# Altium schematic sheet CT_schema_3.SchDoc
size 573 x 363 mm
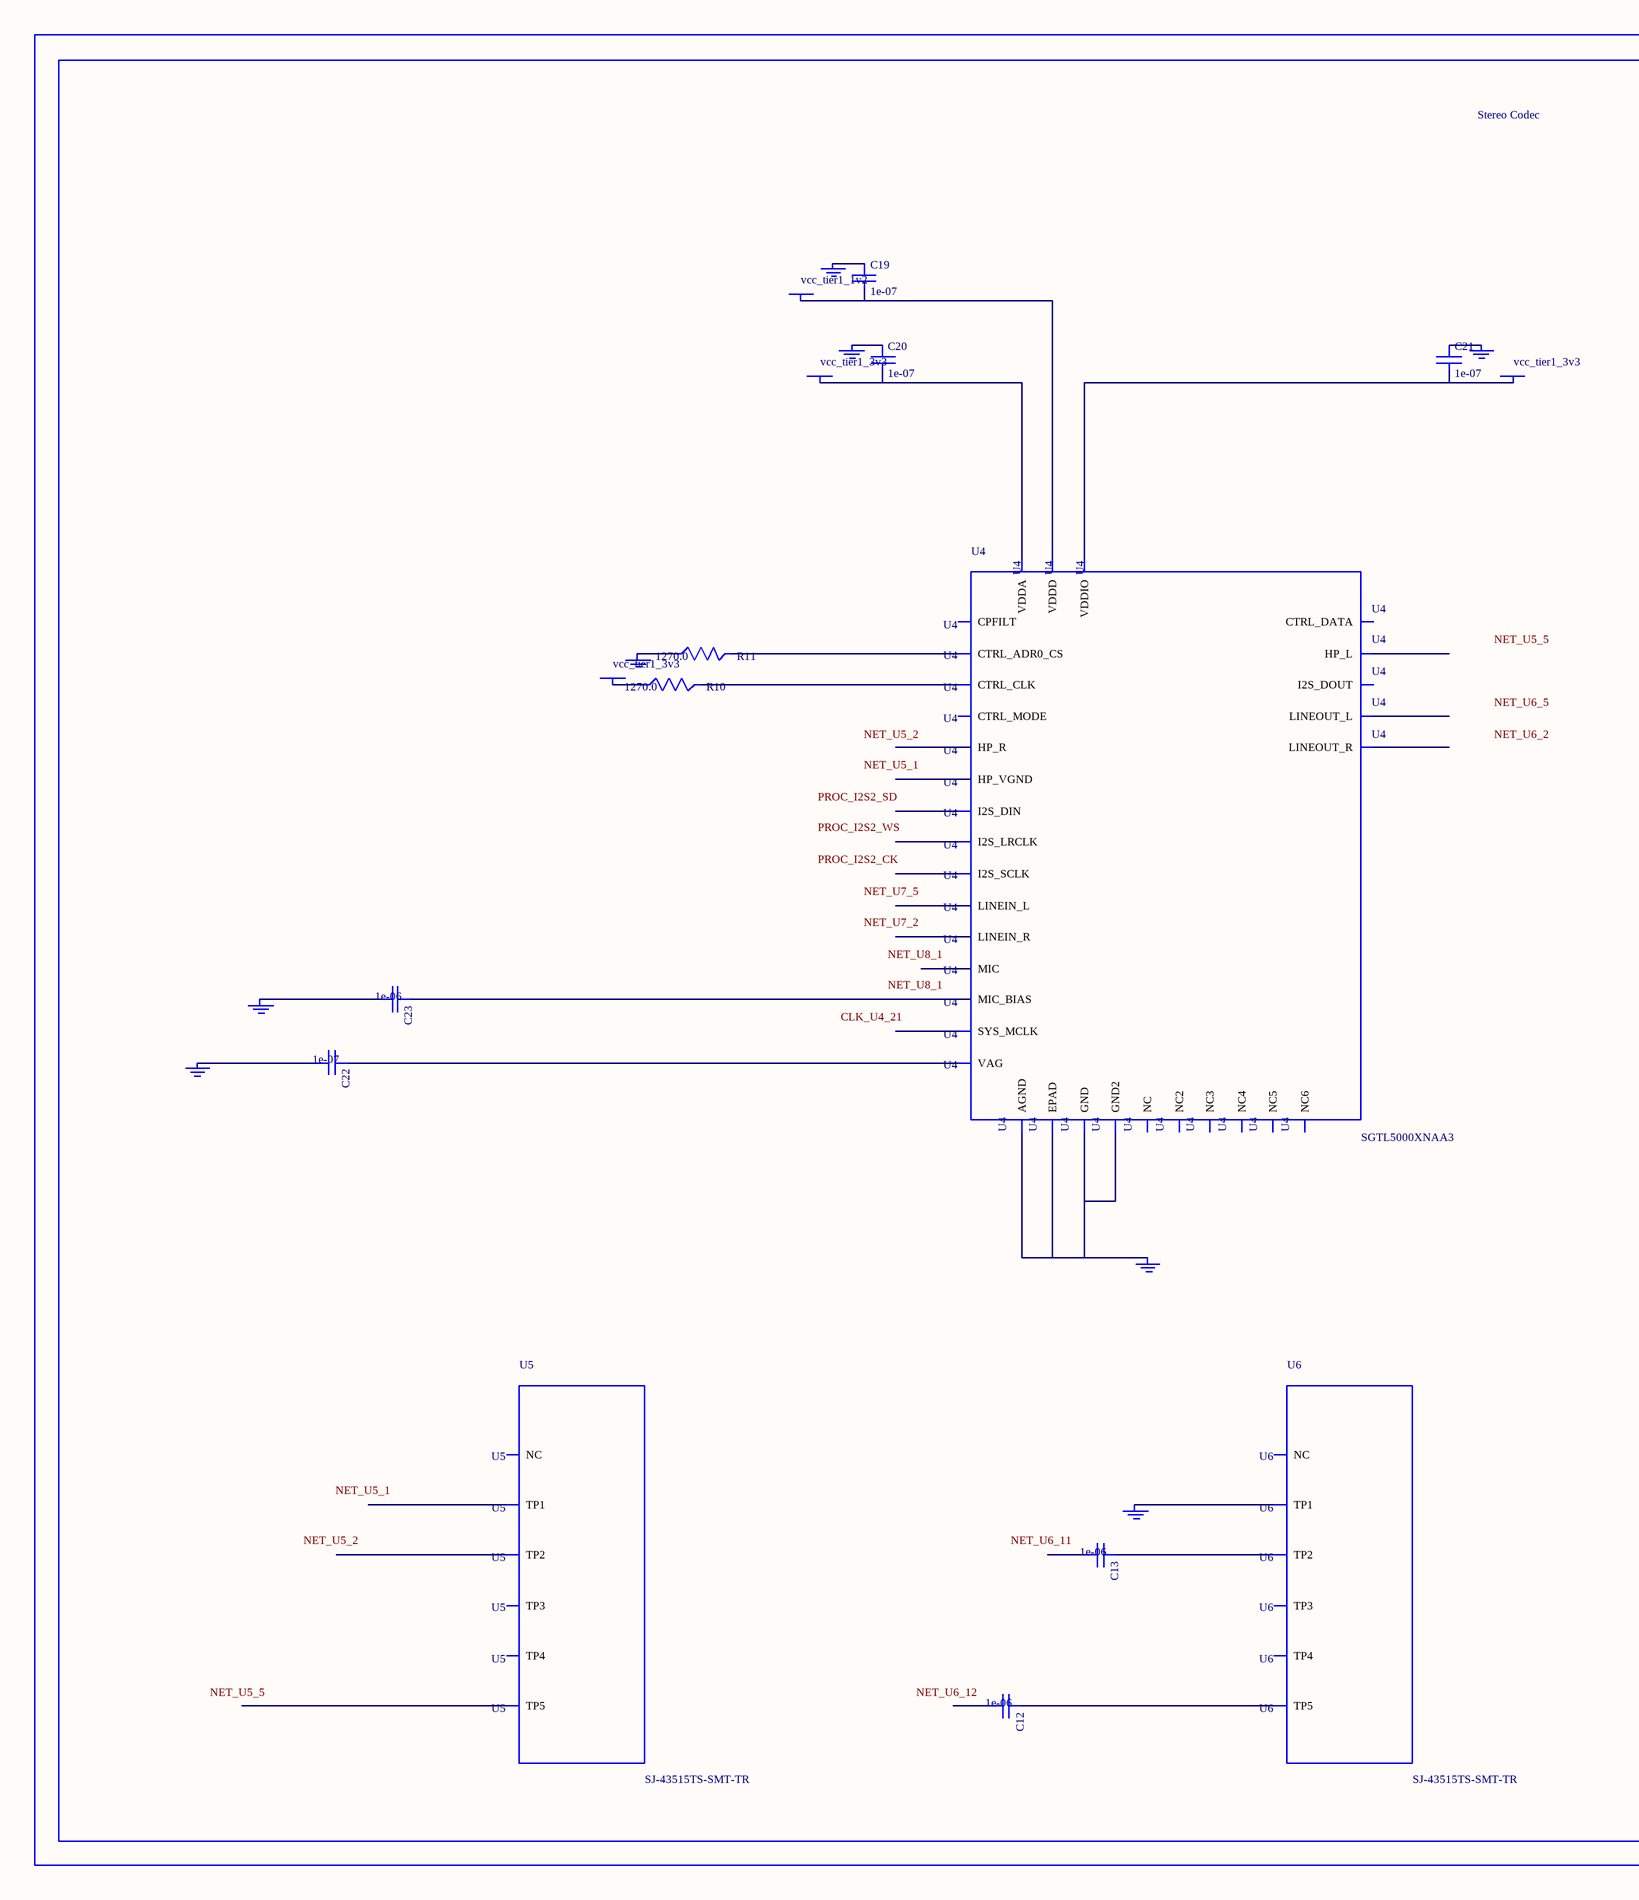
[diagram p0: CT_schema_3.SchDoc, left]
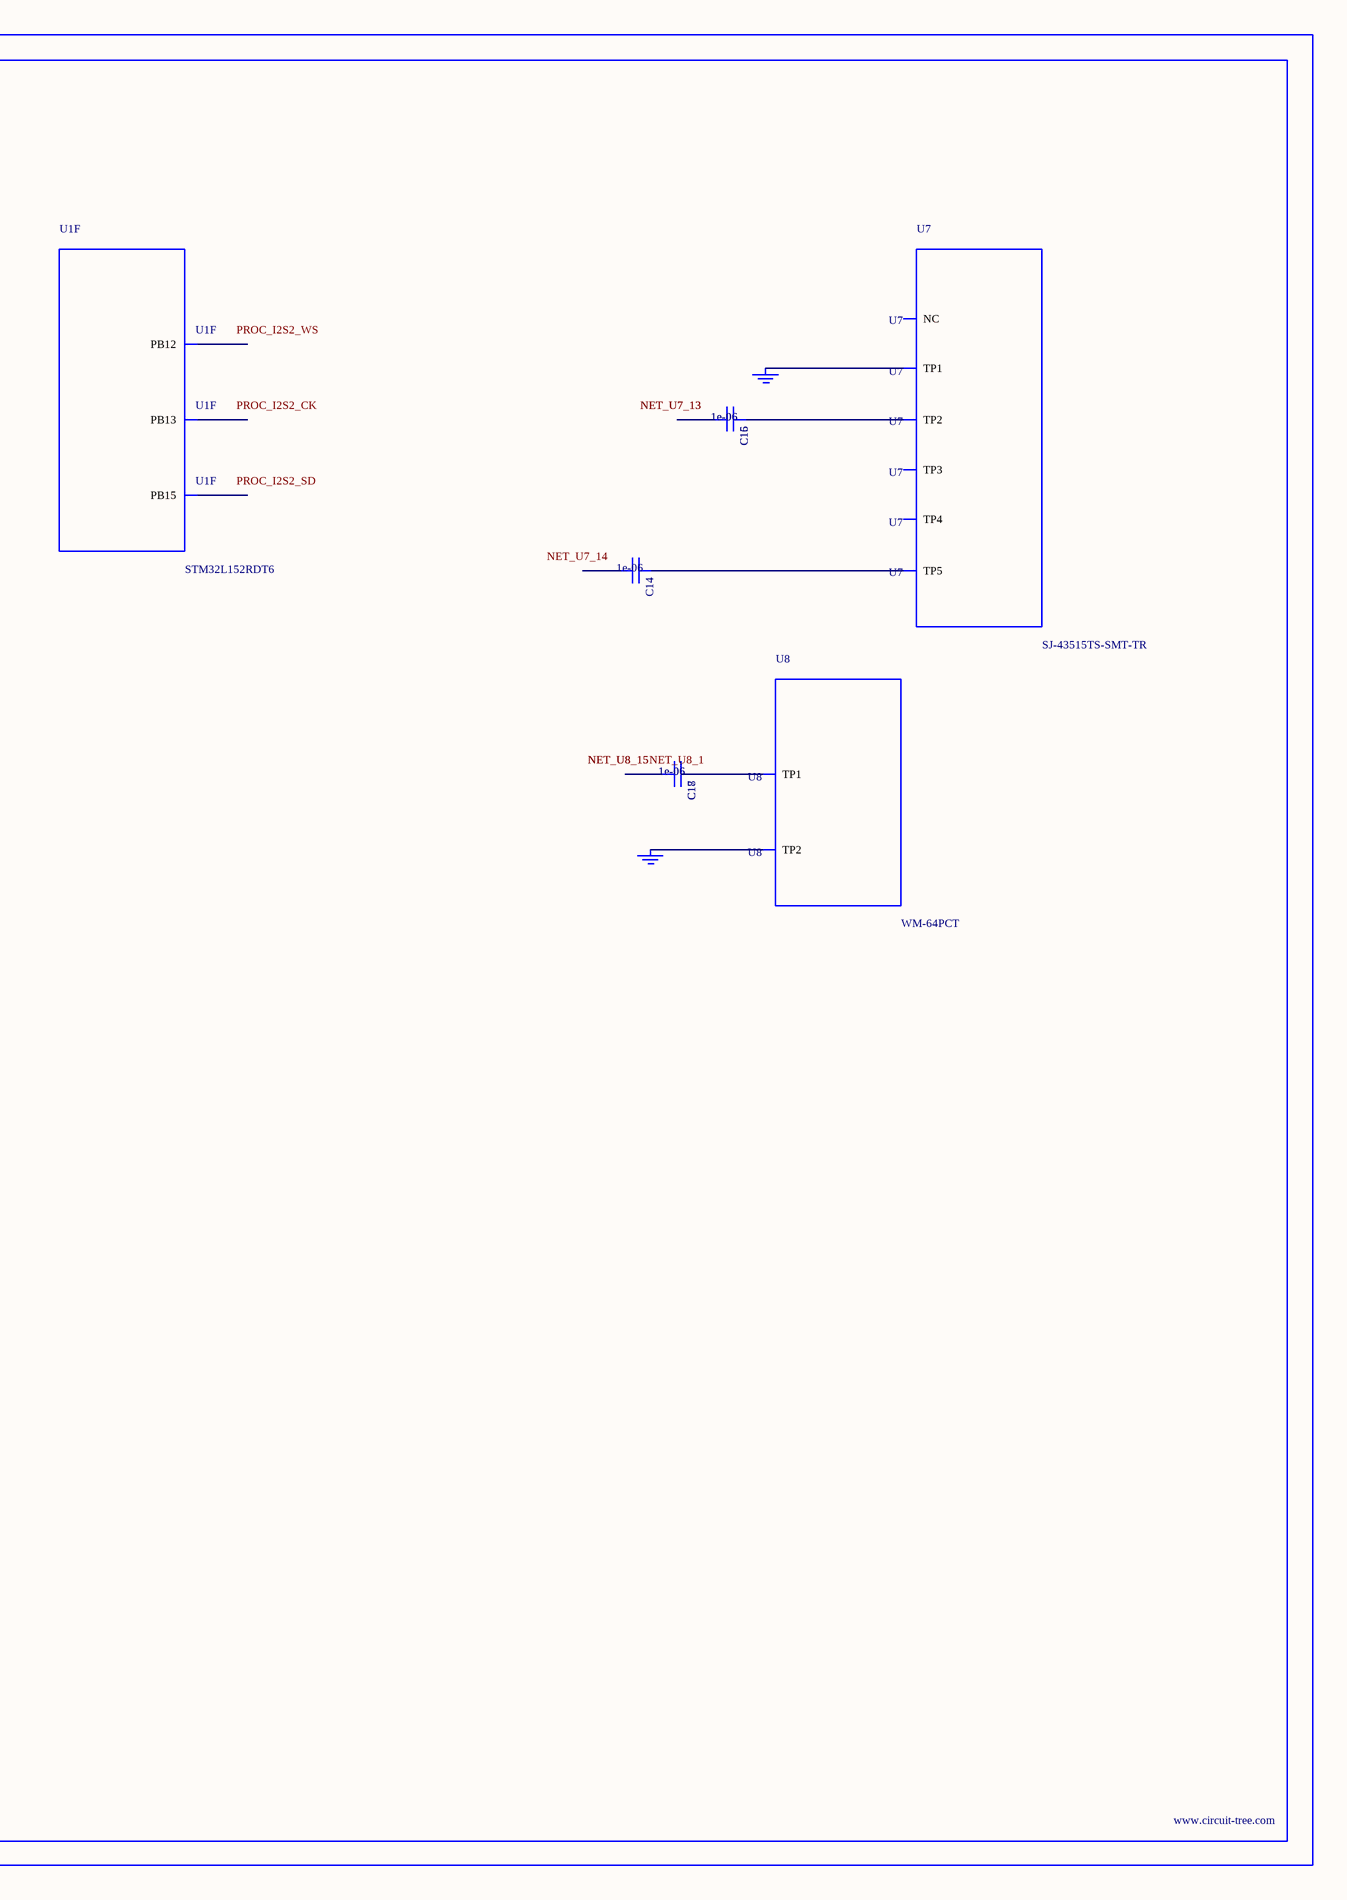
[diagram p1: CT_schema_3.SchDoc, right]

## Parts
BORDER2  (no value)
C12  1e-06  [C0603]
C13  1e-06  [C0603]
C14  1e-06  [C0603]
C15  1e-06  [C0603]
C16  1e-06  [C0603]
C17  1e-06  [C0603]
C18  1e-06  [C0603]
C19  1e-07  [C0402]
C20  1e-07  [C0402]
C21  1e-07  [C0402]
C22  1e-07  [C0402]
C23  1e-06  [C0603]
GND_INSTANCE_2_0  (no value)
GND_INSTANCE_2_1  (no value)
GND_INSTANCE_2_2  (no value)
GND_INSTANCE_2_3  (no value)
GND_INSTANCE_2_4  (no value)
GND_INSTANCE_2_5  (no value)
GND_INSTANCE_2_6  (no value)
GND_INSTANCE_2_7  (no value)
GND_INSTANCE_2_8  (no value)
GND_INSTANCE_2_9  (no value)
GND_INSTANCE_2_10  (no value)
POWER_INSTANCE_2_0  vcc_tier1_3v3
POWER_INSTANCE_2_1  vcc_tier1_3v3
POWER_INSTANCE_2_2  vcc_tier1_3v3
POWER_INSTANCE_2_3  vcc_tier1_1v2
R10  1270.0  [R0603]
R11  1270.0  [R0603]
U1  STM32L152RDT6  [LQFP64]  (part F of 7)
U4  SGTL5000XNAA3  [QFN-32]
U5  SJ-43515TS-SMT-TR  [SJ-43515TS-SMT-TR]
U6  SJ-43515TS-SMT-TR  [SJ-43515TS-SMT-TR]
U7  SJ-43515TS-SMT-TR  [SJ-43515TS-SMT-TR]
U8  WM-64PCT  [WM-64PC]

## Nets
NetC12_1: C12.1 U6.5(TP5)
NetC13_1: C13.1 U6.2(TP2)
NetC14_1: C14.1 U7.5(TP5)
NetC15_1: C15.1 C16.1 U7.2(TP2)
NetC15_2: C15.2 C16.2
NetC17_1: C17.1 C18.1 U8.1(TP1)
NetC17_2: C17.2 C18.2
NetC19_1: C19.1 GND_INSTANCE_2_5.0(GND)
NetC19_2: C19.2 POWER_INSTANCE_2_3.0(PWR) U4.30(VDDD)
NetC20_1: C20.1 GND_INSTANCE_2_1.0(GND)
NetC20_2: C20.2 POWER_INSTANCE_2_0.0(PWR) U4.5(VDDA)
NetC21_1: C21.1 GND_INSTANCE_2_4.0(GND)
NetC21_2: C21.2 POWER_INSTANCE_2_1.0(PWR) U4.20(VDDIO)
NetC22_1: C22.1 U4.10(VAG)
NetC22_2: C22.2 GND_INSTANCE_2_2.0(GND)
NetC23_1: C23.1 U4.16(MIC_BIAS)
NetC23_2: C23.2 GND_INSTANCE_2_3.0(GND)
NetGND_INSTANCE_2_0_0: GND_INSTANCE_2_0.0(GND) U4.1(GND) U4.3(GND2) U4.7(AGND) U4.EXP(EPAD)
NetGND_INSTANCE_2_6_0: GND_INSTANCE_2_6.0(GND) R11.1
NetGND_INSTANCE_2_7_0: GND_INSTANCE_2_7.0(GND) U6.1(TP1)
NetGND_INSTANCE_2_8_0: GND_INSTANCE_2_8.0(GND) GND_INSTANCE_2_9.0(GND) U7.1(TP1)
NetGND_INSTANCE_2_10_0: GND_INSTANCE_2_10.0(GND) U8.2(TP2)
NetPOWER_INSTANCE_2_2_0: POWER_INSTANCE_2_2.0(PWR) R10.1
NetR10_2: R10.2 U4.29(CTRL_CLK)
NetR11_2: R11.2 U4.31(CTRL_ADR0_CS)

Not connected (* = marked no-connect by the designer): C12 2; C13 2; C14 2; U1 33(PB12) 34(PB13) 36(PB15); U4 2(HP_R) 4(HP_VGND) 6(HP_L) 8(NC) 9(NC2) 11(LINEOUT_R) 12(LINEOUT_L) 13(LINEIN_R) 14(LINEIN_L) 15(MIC) 17(NC3) 18(CPFILT) 19(NC4) 21(SYS_MCLK) 22(NC5) 23(I2S_LRCLK) 24(I2S_SCLK) 25(I2S_DOUT) 26(I2S_DIN) 27(CTRL_DATA) 28(NC6) 32(CTRL_MODE); U5 1(TP1) 2(TP2) 3(TP3) 4(TP4) 5(TP5) 6(NC); U6 3(TP3) 4(TP4) 6(NC); U7 3(TP3) 4(TP4) 6(NC)

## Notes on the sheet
- Labels drawn without touching a wire or pin: CLK_U4_21, NET_U5_1, NET_U5_2, NET_U5_5, NET_U6_2, NET_U6_5, NET_U6_11, NET_U6_12, NET_U7_2, NET_U7_5, NET_U7_14, NET_U8_1, PROC_I2S2_CK, PROC_I2S2_SD, PROC_I2S2_WS

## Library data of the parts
BORDER2 = BORDER_PAGE2
C12-C18 C23 = C0603C105K3RACTU
C19-C22 = C0402C104K3RACTU
GND_INSTANCE_2_0-GND_INSTANCE_2_10 = GND
POWER_INSTANCE_2_0-POWER_INSTANCE_2_3 = PWR
R10 R11 = RC0603FR-071K27L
